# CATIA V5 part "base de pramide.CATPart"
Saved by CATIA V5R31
Part number: base de pramide
Bounding box of the stored display mesh (mm): x -117 to 117, y -81.6 to 81.6, z 0 to 3.3
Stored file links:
  C:\Users\189361\Desktop\piezas del comedero\piezas del comedero\base de pramide.CATPart
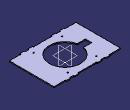
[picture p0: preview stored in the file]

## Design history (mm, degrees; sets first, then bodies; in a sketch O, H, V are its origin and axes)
Body1 (main body)
  Sketch1 on xy-plane, origin (0, 0, 0), H (1, 0, 0), V (0, 1, 0)
    point P1 (0, -78.3)
    line L1 (0, -78.3) -> (-32.35, -78.3)
    point P2 (-32.35, -78.3)
    line L2 (-32.35, -78.3) -> (-32.35, -81.6)
    point P3 (-32.35, -81.6)
    line L3 (-32.35, -81.6) -> (-47.65, -81.6)
    point P4 (-47.65, -81.6)
    line L4 (-47.65, -81.6) -> (-47.65, -78.3)
    point P5 (-47.65, -78.3)
    line L5 (-47.65, -78.3) -> (-62.35, -78.3)
    point P6 (-62.35, -78.3)
    line L6 (-62.35, -78.3) -> (-62.35, -81.6)
    point P7 (-62.35, -81.6)
    line L7 (-62.35, -81.6) -> (-77.65, -81.6)
    point P8 (-77.65, -81.6)
    line L8 (-77.65, -81.6) -> (-77.65, -78.3)
    point P9 (-77.65, -78.3)
    line L9 (-77.65, -78.3) -> (-117, -78.3)
    point P10 (-117, -78.3)
    line L10 (-117, -78.3) -> (-117, 0)
    point P11 (-117, 0)
    construction line L11 (-40, -76.955) -> (-40, -50.741)
    point P12 (-40, -76.955)
    point P13 (-40, -50.741)
    construction line L12 (-70, -82.6649) -> (-70, -41.6569)
    point P14 (-70, -82.6649)
    point P15 (-70, -41.6569)
    point P16 (0, 0)
    point P17 (0, -78.3)
    point P18 (32.35, -78.3)
    point P19 (32.35, -81.6)
    point P20 (47.65, -81.6)
    point P21 (47.65, -78.3)
    point P22 (62.35, -78.3)
    point P23 (62.35, -81.6)
    point P24 (77.65, -81.6)
    point P25 (77.65, -78.3)
    point P26 (117, -78.3)
    point P27 (117, 0)
    point P28 (40, -50.741)
    point P29 (40, -76.955)
    construction line L13 (40, -76.955) -> (40, -50.741)
    point P30 (70, -41.6569)
    point P31 (70, -82.6649)
    construction line L14 (70, -82.6649) -> (70, -41.6569)
    line L15 (0, -78.3) -> (32.35, -78.3)
    line L16 (32.35, -78.3) -> (32.35, -81.6)
    line L17 (32.35, -81.6) -> (47.65, -81.6)
    line L18 (47.65, -81.6) -> (47.65, -78.3)
    line L19 (47.65, -78.3) -> (62.35, -78.3)
    line L20 (62.35, -78.3) -> (62.35, -81.6)
    line L21 (62.35, -81.6) -> (77.65, -81.6)
    line L22 (77.65, -81.6) -> (77.65, -78.3)
    line L23 (77.65, -78.3) -> (117, -78.3)
    line L24 (117, -78.3) -> (117, 0)
    point P32 (0, 78.3)
    point P33 (-32.35, 78.3)
    point P34 (-32.35, 81.6)
    point P35 (-47.65, 81.6)
    point P36 (-47.65, 78.3)
    point P37 (-62.35, 78.3)
    point P38 (-62.35, 81.6)
    point P39 (-77.65, 81.6)
    point P40 (-77.65, 78.3)
    point P41 (-117, 78.3)
    point P42 (-40, 76.955)
    point P43 (-70, 82.6649)
    point P44 (0, 78.3)
    point P45 (32.35, 78.3)
    point P46 (32.35, 81.6)
    point P47 (47.65, 81.6)
    point P48 (47.65, 78.3)
    point P49 (62.35, 78.3)
    point P50 (62.35, 81.6)
    point P51 (77.65, 81.6)
    point P52 (77.65, 78.3)
    point P53 (117, 78.3)
    point P54 (40, 76.955)
    point P55 (70, 82.6649)
    line L25 (0, 78.3) -> (-32.35, 78.3)
    line L26 (-32.35, 78.3) -> (-32.35, 81.6)
    line L27 (-32.35, 81.6) -> (-47.65, 81.6)
    line L28 (-47.65, 81.6) -> (-47.65, 78.3)
    line L29 (-47.65, 78.3) -> (-62.35, 78.3)
    line L30 (-62.35, 78.3) -> (-62.35, 81.6)
    line L31 (-62.35, 81.6) -> (-77.65, 81.6)
    line L32 (-77.65, 81.6) -> (-77.65, 78.3)
    line L33 (-77.65, 78.3) -> (-117, 78.3)
    line L34 (0, 78.3) -> (32.35, 78.3)
    line L35 (32.35, 78.3) -> (32.35, 81.6)
    line L36 (32.35, 81.6) -> (47.65, 81.6)
    line L37 (47.65, 81.6) -> (47.65, 78.3)
    line L38 (47.65, 78.3) -> (62.35, 78.3)
    line L39 (62.35, 78.3) -> (62.35, 81.6)
    line L40 (62.35, 81.6) -> (77.65, 81.6)
    line L41 (77.65, 81.6) -> (77.65, 78.3)
    line L42 (77.65, 78.3) -> (117, 78.3)
    point P56 (-117, 0)
    line L43 (-117, 78.3) -> (-117, 0)
    point P57 (117, 0)
    line L44 (117, 78.3) -> (117, 0)
    arc A1 centre (0, 0) radius 55 from (-53.8888, -11) to (-53.8888, 11) ccw
    axis line L45 (0, 0) -> (-83, 0)
    point P58 (-83, 0)
    line L46 (-53.8888, 11) -> (-83, 11)
    line L47 (-83, 11) -> (-83, -11)
    line L48 (-83, -11) -> (-53.8888, -11)
    length L3 = 15.3
    distance L11 L2 = 7.65
    distance L11 V = 40
    distance L12 L8 = 7.65
    distance L11 L12 = 30
    distance V L10 = 117
    distance L1 H = 78.3
    length L8 = 3.3
    radius A1 = 55
    length L45 = 83
    length L47 = 22
    distance L46 L45 = 11
    coincidence: P1 V, P5 L1, P7 L3, P9 L1, P11 H, P1 P17, P11 P56, P27 P57, P32 P44, L47 P58
    horizontal: L1 H, L3 H, L5 H, L7 H, L9 H, L45 H, L46 H, L48 H
    vertical: L2 V, L4 V, L6 V, L8 V, L10 V, L11 V, L12 V, L47 V
    equal size: L3 L7
    symmetry: O P16 V, P1 P17 V, P2 P18 V, P3 P19 V, P4 P20 V, P5 P21 V, P6 P22 V, P7 P23 V, P8 P24 V, P9 P25 V, P10 P26 V, P11 P27 V, P13 P28 V, P12 P29 V, L11 L13 V, P15 P30 V, P14 P31 V, L12 L14 V, L1 L15 V, L2 L16 V, L3 L17 V, L4 L18 V, L5 L19 V, L6 L20 V, L7 L21 V, L8 L22 V, L9 L23 V, L10 L24 V, P1 P32 H, P2 P33 H, P3 P34 H, P4 P35 H, P5 P36 H, P6 P37 H, P7 P38 H, P8 P39 H, P9 P40 H, P10 P41 H, P12 P42 H, P14 P43 H, P17 P44 H, P18 P45 H, P19 P46 H, P20 P47 H, P21 P48 H, P22 P49 H, P23 P50 H, P24 P51 H, P25 P52 H, P26 P53 H, P29 P54 H, P31 P55 H, L1 L25 H, L2 L26 H, L3 L27 H, L4 L28 H, L5 L29 H, L6 L30 H, L7 L31 H, L8 L32 H, L9 L33 H, L15 L34 H, L16 L35 H, L17 L36 H, L18 L37 H, L19 L38 H, L20 L39 H, L21 L40 H, L22 L41 H, L23 L42 H, P11 P56 H, L10 L43 H, P27 P57 H, L24 L44 H
  Pad1: profile Sketch1, direction (0, 0, 1), length 3.3
  Sketch2 on start face of Pad1, origin (0, 0, 0), H (1, 0, 0), V (0, -1, 0)
    circle A1 centre (-50, 60) radius 2.15
    circle A2 centre (50, 60) radius 2.15
    point P2 (50, 60)
    axis line L1 (-50, 60) -> (50, 60)
    point P3 (50, 60)
    circle A3 centre (50, -60) radius 2.15
    circle A4 centre (-50, -60) radius 2.15
    radius A2 = 2.15
    distance H L1 = 60
    length L1 = 100
    distance V P2 = 50
    equal size: A1 A2
    horizontal: L1 H
    coincidence: P2 L1, P3 P2
    symmetry: A2 A3 H, A1 A4 H
  Pocket1: profile Sketch2, direction (0, 0, 1), length 3.3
